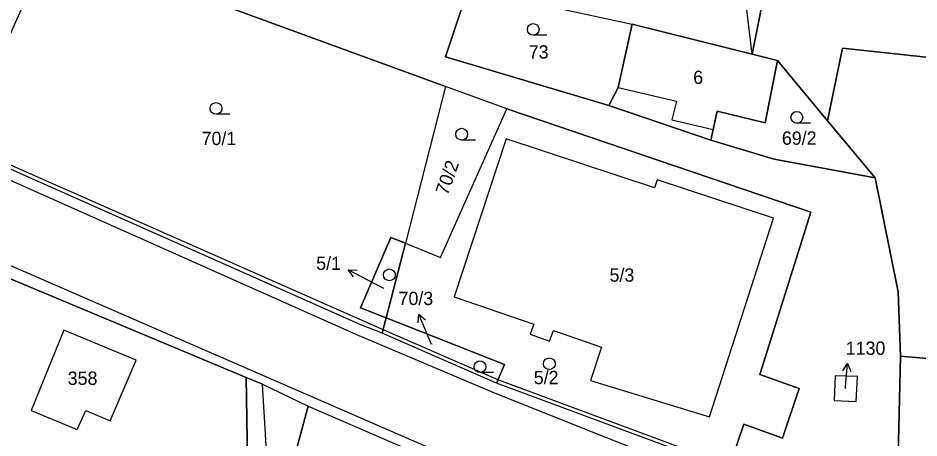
# Model space of a CAD drawing. Extents: x -654083 to -650132, y -1099819 to -1096699.
# Drawn here: x -652350.7 to -652235.7, y -1097974.5 to -1097920.9 of the extents above; entities that cross this region are included whole.
import ezdxf

# ---------------------------------------------------------------- set-up
doc = ezdxf.new("R2010")
doc.units = 0
for name, color, linetype in [('Hranice - vnitř_ kresba', 7, 'Continuous'), ('Obvody jako plochy', 7, 'Continuous'), ('Ostatní hranice', 7, 'Continuous'), ('Parcelní čísla', 7, 'Continuous'), ('Prvky pro prodl_ par_ č_', 7, 'Continuous'), ('Značky kultur', 7, 'Continuous')]:
    doc.layers.add(name, color=color, linetype=linetype)

msp = doc.modelspace()

# ---------------------------------------------------------------- linework, layer by layer
at = {"layer": 'Hranice - vnitř_ kresba'}
for p, q in [((-652274.04, -1097929.73), (-652266.62, -1097931.5)), ((-652266.62, -1097931.5), (-652267.18, -1097933.88)), ((-652267.18, -1097933.88), (-652261.92, -1097935.13)), ((-652358.47, -1097938.54), (-652307.46, -1097961.3)), ((-652361.94, -1097947.99), (-652288.25, -1097980.07)), ((-652307.46, -1097961.3), (-652289.75, -1097968.8)), ((-652289.75, -1097968.8), (-652260.61, -1097980.42))]:
    msp.add_line(p, q, dxfattribs=at)
at = {"layer": 'Obvody jako plochy'}
for points in [[(-652259.95, -1097978.53), (-652289.58, -1097967.54), (-652304.17, -1097961.16), (-652306.89, -1097960.07), (-652358.06, -1097937.32), (-652361.99, -1097934.98), (-652373.04, -1097930.17), (-652374.25, -1097929.65), (-652375.24, -1097929.22), (-652386.86, -1097924.16), (-652403.6, -1097916.6), (-652409.91, -1097913.27), (-652436.78, -1097901.48), (-652463.96, -1097889.56), (-652483.6, -1097880.94), (-652534, -1097858.11), (-652537.59, -1097856.5), (-652554.49, -1097848.9), (-652581.83, -1097835.42), (-652676.84, -1097793.83), (-652695.77, -1097785.5), (-652811.07, -1097733.73)], [(-652293.2, -1097917.08), (-652296.1, -1097925.82), (-652275.24, -1097932.05), (-652262.2, -1097936.47), (-652254.14, -1097938.89), (-652241.24, -1097941.29), (-652238.29, -1097955.86), (-652238.02, -1097964.08), (-652238.44, -1097982.36), (-652234.52, -1097986.28), (-652259.95, -1097978.53), (-652258, -1097972.76), (-652253.08, -1097974.55), (-652250.95, -1097968.2), (-652255.98, -1097966.41), (-652249.44, -1097945.69), (-652288.28, -1097932.49), (-652296.09, -1097929.62), (-652346.41, -1097911.18)], [(-652352.33, -1097953.9), (-652321.55, -1097966.79), (-652319.45, -1097967.67), (-652313.63, -1097970.49), (-652296.29, -1097977.99), (-652290.75, -1097980.73), (-652288.8, -1097981.69), (-652259.27, -1097990.89), (-652256.18, -1097991.8), (-652254.6, -1097992.33), (-652249.29, -1097994.09), (-652245.37, -1097995.39), (-652238.28, -1097998.5), (-652228.88, -1098001.59), (-652216.37, -1098004.62), (-652210.39, -1098007.21), (-652202.83, -1098010.48), (-652188.53, -1098014.39), (-652179.79, -1098016.9), (-652162.7, -1098022.58)]]:
    msp.add_lwpolyline(points, dxfattribs=at)
for points in [[(-652168.06, -1097813.81), (-652190.97, -1097887.21), (-652209.11, -1097928.62), (-652245.4, -1097924.7), (-652247.31, -1097933.99), (-652253.71, -1097926.28), (-652256.94, -1097925.47), (-652250.42, -1097892.82), (-652243.6, -1097858.64), (-652238.49, -1097829), (-652245.39, -1097822.57), (-652237.89, -1097811.35), (-652229.64, -1097803.39), (-652221.54, -1097793.79), (-652210.98, -1097793.09), (-652198.1, -1097797.24)], [(-652272.28, -1097921.65), (-652256.94, -1097925.47), (-652261.76, -1097885.23), (-652284.24, -1097892.9), (-652265.64, -1097903.03), (-652269.6, -1097909.81), (-652272.24, -1097914.33), (-652283.93, -1097905.25), (-652290.08, -1097908.86), (-652293.2, -1097917.08)], [(-652250.42, -1097892.82), (-652256.94, -1097925.47), (-652261.76, -1097885.23)], [(-652306.95, -1097957.89), (-652303.66, -1097959.19), (-652304.17, -1097961.16), (-652306.89, -1097960.07), (-652358.06, -1097937.32), (-652346.41, -1097911.18), (-652296.09, -1097929.62), (-652301.21, -1097949.62), (-652303.07, -1097948.9)], [(-652274.04, -1097929.73), (-652275.24, -1097932.05), (-652296.1, -1097925.82), (-652293.2, -1097917.08), (-652272.28, -1097921.65)], [(-652261.92, -1097935.13), (-652262.2, -1097936.47), (-652275.24, -1097932.05), (-652274.04, -1097929.73), (-652272.28, -1097921.65), (-652256.94, -1097925.47), (-652253.71, -1097926.28), (-652255.27, -1097934.26), (-652261.42, -1097932.76)], [(-652261.42, -1097932.76), (-652255.27, -1097934.26), (-652253.71, -1097926.28), (-652256.94, -1097925.47), (-652272.28, -1097921.65), (-652274.04, -1097929.73), (-652266.62, -1097931.5), (-652267.18, -1097933.88), (-652261.92, -1097935.13)], [(-652247.31, -1097933.99), (-652245.4, -1097924.7), (-652209.11, -1097928.62), (-652211.08, -1097933.1), (-652207.96, -1097950.71), (-652221.17, -1097947.16), (-652226.1, -1097963.61), (-652230.05, -1097962.51), (-652230.59, -1097964.7), (-652238.02, -1097964.08), (-652238.29, -1097955.86), (-652241.24, -1097941.29)], [(-652253.71, -1097926.28), (-652247.31, -1097933.99), (-652241.24, -1097941.29), (-652254.14, -1097938.89), (-652262.2, -1097936.47), (-652261.92, -1097935.13), (-652261.42, -1097932.76), (-652255.27, -1097934.26)], [(-652296.71, -1097951.48), (-652288.28, -1097932.49), (-652296.09, -1097929.62), (-652301.21, -1097949.62)], [(-652258, -1097972.76), (-652259.95, -1097978.53), (-652289.58, -1097967.54), (-652288.57, -1097965.14), (-652303.66, -1097959.19), (-652301.21, -1097949.62), (-652296.71, -1097951.48), (-652288.28, -1097932.49), (-652249.44, -1097945.69), (-652255.98, -1097966.41), (-652250.95, -1097968.2), (-652253.08, -1097974.55)], [(-652285.27, -1097961.27), (-652282.8, -1097962.15), (-652282.31, -1097960.82), (-652276.18, -1097962.91), (-652277.59, -1097967.18), (-652262.39, -1097971.83), (-652254.24, -1097946.43), (-652269.08, -1097941.54), (-652269.4, -1097942.58), (-652288.34, -1097936.31), (-652294.97, -1097956.48), (-652284.81, -1097959.97)], [(-652269.4, -1097942.58), (-652288.34, -1097936.31), (-652294.97, -1097956.48), (-652284.81, -1097959.97), (-652285.27, -1097961.27), (-652282.8, -1097962.15), (-652282.31, -1097960.82), (-652276.18, -1097962.91), (-652277.59, -1097967.18), (-652262.39, -1097971.83), (-652254.24, -1097946.43), (-652269.08, -1097941.54)], [(-652288.34, -1097936.31), (-652294.97, -1097956.48), (-652284.81, -1097959.97), (-652285.27, -1097961.27), (-652282.8, -1097962.15), (-652282.31, -1097960.82), (-652276.18, -1097962.91), (-652277.59, -1097967.18), (-652262.39, -1097971.83), (-652254.24, -1097946.43), (-652269.08, -1097941.54), (-652269.4, -1097942.58)], [(-652301.21, -1097949.62), (-652303.66, -1097959.19), (-652306.95, -1097957.89), (-652303.07, -1097948.9)], [(-652342.75, -1097987.96), (-652341.4, -1097983.51), (-652339.55, -1097977.37), (-652330.83, -1097979.83), (-652330.17, -1097977.59), (-652324.69, -1097979.27), (-652325.26, -1097981.36), (-652321.28, -1097982.55), (-652321.55, -1097966.79), (-652352.33, -1097953.9), (-652357.13, -1097966.99), (-652348.97, -1097985.81)], [(-652288.57, -1097965.14), (-652289.58, -1097967.54), (-652304.17, -1097961.16), (-652303.66, -1097959.19)], [(-652348.96, -1097971.03), (-652343.1, -1097973.47), (-652341.99, -1097971.03), (-652338.87, -1097972.34), (-652335.57, -1097964.61), (-652344.81, -1097960.76)], [(-652344.81, -1097960.76), (-652348.96, -1097971.03), (-652343.1, -1097973.47), (-652341.99, -1097971.03), (-652338.87, -1097972.34), (-652335.57, -1097964.61)], [(-652335.57, -1097964.61), (-652344.81, -1097960.76), (-652348.96, -1097971.03), (-652343.1, -1097973.47), (-652341.99, -1097971.03), (-652338.87, -1097972.34)], [(-652238.02, -1097964.08), (-652230.59, -1097964.7), (-652234.19, -1097976.37), (-652221.93, -1097979.58), (-652222.11, -1097989.35), (-652234.52, -1097986.28), (-652238.44, -1097982.36)], [(-652318.49, -1097983.28), (-652319.45, -1097967.67), (-652321.55, -1097966.79), (-652321.28, -1097982.55)], [(-652243.66, -1097969.88), (-652243.52, -1097966.7), (-652246.36, -1097966.59), (-652246.48, -1097969.74)], [(-652243.52, -1097966.7), (-652246.36, -1097966.59), (-652246.48, -1097969.74), (-652243.66, -1097969.88)], [(-652313.63, -1097970.49), (-652316.25, -1097980.24), (-652314.85, -1097980.77), (-652320.34, -1097996.7), (-652313.51, -1097999.5), (-652319.32, -1098003.34), (-652320.87, -1098000.27), (-652325.04, -1097996.04), (-652323.7, -1097989.88), (-652321.28, -1097982.55), (-652318.49, -1097983.28), (-652319.45, -1097967.67)], [(-652313.63, -1097970.49), (-652296.29, -1097977.99), (-652307.72, -1097992.1), (-652310.44, -1097991.02), (-652305.96, -1097978.67), (-652313.17, -1097975.9), (-652314.85, -1097980.77), (-652316.25, -1097980.24)]]:
    msp.add_lwpolyline(points, close=True, dxfattribs=at)
for centre, radius in [((-652303.26, -1097953.69), 0.75), ((-652303.26, -1097953.69), 0.001), ((-652282.84, -1097965.05), 0.75), ((-652282.84, -1097965.05), 0.001)]:
    msp.add_circle(centre, radius, dxfattribs=at)
at = {"layer": 'Ostatní hranice'}
for p, q in [((-652357.82, -1097936.88), (-652303.89, -1097960.75)), ((-652303.89, -1097960.75), (-652289.34, -1097967.1)), ((-652289.34, -1097967.1), (-652259.75, -1097978.07))]:
    msp.add_line(p, q, dxfattribs=at)
at = {"layer": 'Prvky pro prodl_ par_ č_'}
for p, q in [((-652305.85, -1097954.45), (-652308.5, -1097953.05)), ((-652303.96, -1097955.45), (-652305.85, -1097954.45)), ((-652298.34, -1097961.48), (-652299.49, -1097958.71)), ((-652297.88, -1097962.6), (-652298.34, -1097961.48)), ((-652245.03, -1097967.99), (-652244.76, -1097965)), ((-652245.05, -1097968.2), (-652245.03, -1097967.99))]:
    msp.add_line(p, q, dxfattribs=at)
for points in [[(-652307.85, -1097953.96), (-652308.5, -1097953.05), (-652307.38, -1097953.07)], [(-652299.57, -1097959.82), (-652299.49, -1097958.71), (-652298.64, -1097959.44)], [(-652245.35, -1097965.95), (-652244.76, -1097965), (-652244.35, -1097966.04)]]:
    msp.add_lwpolyline(points, dxfattribs=at)
at = {"layer": 'Značky kultur'}
for p, q in [((-652283.14, -1097923.07), (-652284.89, -1097923.07)), ((-652323.63, -1097933.17), (-652325.38, -1097933.17)), ((-652249.49, -1097934.3), (-652251.24, -1097934.3)), ((-652292.28, -1097936.46), (-652294.03, -1097936.46)), ((-652289.94, -1097966.17), (-652291.69, -1097966.17))]:
    msp.add_line(p, q, dxfattribs=at)
for centre in [(-652284.89, -1097922.32), (-652325.38, -1097932.42), (-652251.24, -1097933.55), (-652294.03, -1097935.71), (-652291.69, -1097965.42)]:
    msp.add_circle(centre, 0.75, dxfattribs=at)

# ---------------------------------------------------------------- texts
at = {"layer": 'Parcelní čísla'}
for s, height, p in [('73', 1.7, (-652285.46, -1097926.05)), ('6', 1.7, (-652264.47, -1097929.29)), ('70/1', 1.7, (-652327.22, -1097937.1)), ('69/2', 1.7, (-652253.15, -1097937.06)), ('5/3', 1.7, (-652275.15, -1097954.56)), ('5/1', 0.1, (-652304.05, -1097955.45)), ('70/3', 0.1, (-652298.03, -1097962.6)), ('5/2', 1.7, (-652284.82, -1097967.66)), ('358', 1.7, (-652344.31, -1097967.75)), ('1130', 0.1, (-652245.16, -1097968.2))]:
    msp.add_text(s, height=height, dxfattribs=at).set_placement(p)
msp.add_text('70/2', height=1.7, rotation=70.38, dxfattribs=at).set_placement((-652295.82, -1097943.61))
at = {"layer": 'Prvky pro prodl_ par_ č_'}
for s, p in [('5/1', (-652312.59, -1097953.05)), ('70/3', (-652302.08, -1097957.55)), ('1130', (-652245, -1097963.91))]:
    msp.add_text(s, height=1.7, dxfattribs=at).set_placement(p)

doc.saveas('drawing.dxf')
